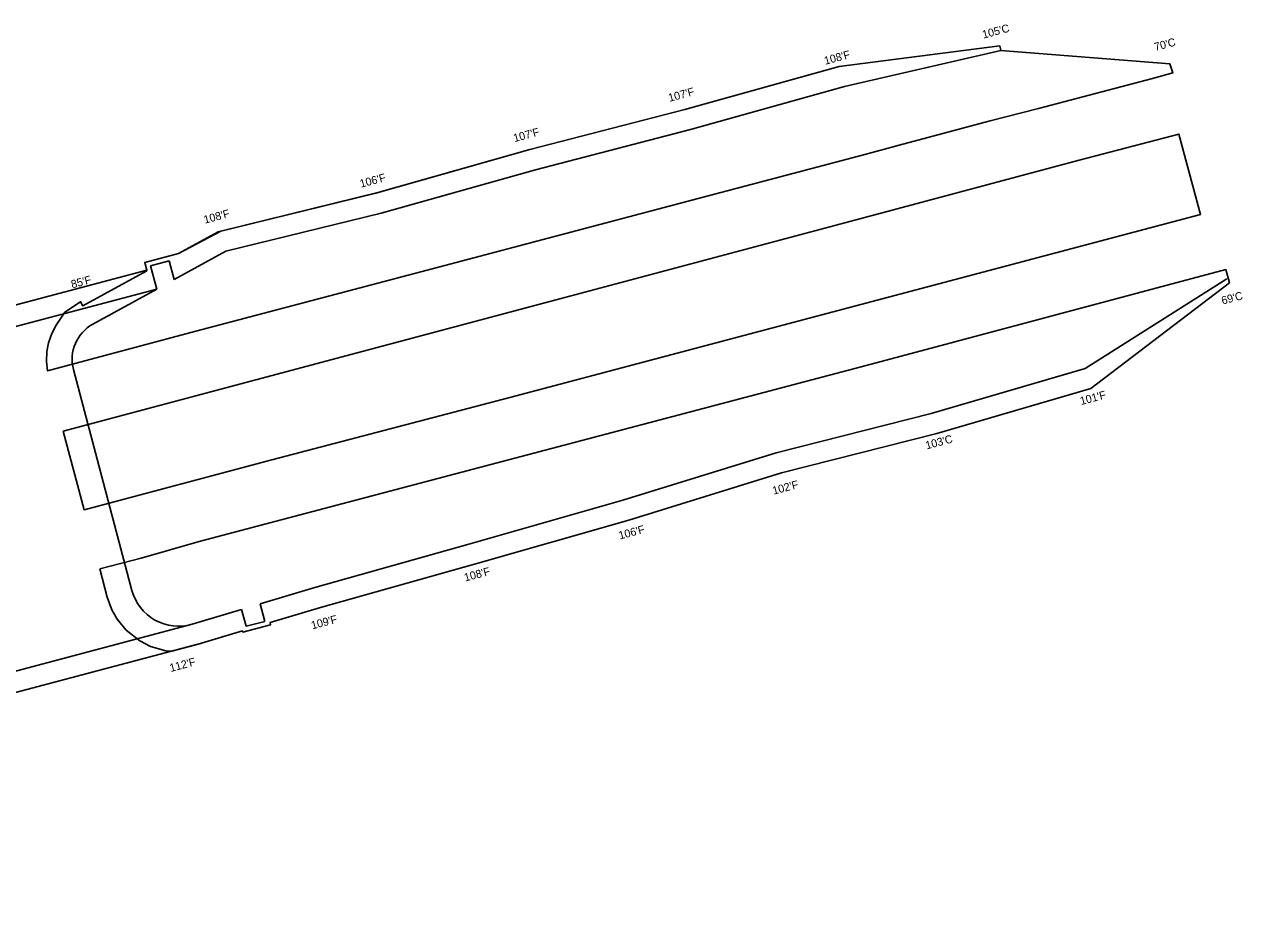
# Model space of a CAD drawing. Extents: x 2110378 to 2113376, y 867150 to 868109.
# Drawn here: x 2112615 to 2113376, y 867557 to 868109 of the extents above; entities that cross this region are included whole.
import ezdxf

# ---------------------------------------------------------------- set-up
doc = ezdxf.new("R2010")
doc.units = 0
for name, color, linetype in [('RD_PD_BCA', 7, 'Continuous'), ('RD_PD_CstnLmt', 7, 'Continuous'), ('RD_PD_DR_ErosCtrl', 7, 'Continuous'), ('RD_PD_TX_CstnLmt', 7, 'Continuous'), ('RD_Sketch1', 7, 'Continuous')]:
    doc.layers.add(name, color=color, linetype=linetype)

msp = doc.modelspace()

# ---------------------------------------------------------------- linework, layer by layer
at = {"layer": 'RD_PD_BCA'}
for p, q in [((2112015.1, 867762.57), (2112698.08, 867943.59)), ((2112108.51, 867572.24), (2112720.22, 867734.37))]:
    msp.add_line(p, q, dxfattribs=at)
at = {"layer": 'RD_PD_CstnLmt'}
for p, q in [((2113127.64, 868070.09), (2113225.16, 868092.49)), ((2113225.16, 868092.49), (2113330.72, 868084.31)), ((2113031.3, 868043.28), (2113127.64, 868070.09)), ((2112934.51, 868018.12), (2113031.3, 868043.28)), ((2112838.26, 867990.93), (2112934.51, 868018.12)), ((2112741.11, 867967.18), (2112838.26, 867990.93)), ((2112694.23, 867958.11), (2112705.83, 867961.18)), ((2112705.83, 867961.18), (2112708.92, 867949.53)), ((2112708.92, 867949.53), (2112741.11, 867967.18)), ((2112698.08, 867943.59), (2112694.23, 867958.11)), ((2113277.77, 867894), (2113366.29, 867950.1)), ((2112658.16, 867921.71), (2112698.08, 867943.59)), ((2112646.01, 867893.38), (2112682.58, 867755.41)), ((2113181.74, 867865.99), (2113277.77, 867894)), ((2113084.79, 867841.46), (2113181.74, 867865.99)), ((2112989.18, 867811.87), (2113084.79, 867841.46)), ((2112893.01, 867784.39), (2112989.18, 867811.87)), ((2112796.72, 867757.37), (2112893.01, 867784.39)), ((2112762.57, 867747.1), (2112796.72, 867757.37)), ((2112720.22, 867734.37), (2112751.07, 867743.64)), ((2112751.07, 867743.64), (2112753.88, 867733.06)), ((2112765.48, 867736.13), (2112762.57, 867747.1)), ((2112753.88, 867733.06), (2112765.48, 867736.13))]:
    msp.add_line(p, q, dxfattribs=at)
for centre, radius, start, end in [((2112670.18, 867899.79), 25, 118.73013, 194.84478), ((2112711.58, 867763.1), 30, 194.84478, 286.73431)]:
    msp.add_arc(centre, radius, start, end, dxfattribs=at)
at = {"layer": 'RD_PD_DR_ErosCtrl'}
for p, q in [((2113124.16, 868082.61), (2113224.49, 868095.41)), ((2113027.92, 868055.83), (2113124.16, 868082.61)), ((2112931.11, 868030.66), (2113027.92, 868055.83)), ((2112834.95, 868003.5), (2112931.11, 868030.66)), ((2112736.36, 867979.4), (2112834.95, 868003.5)), ((2112711.55, 867965.8), (2112736.36, 867979.4)), ((2112690.56, 867960.24), (2112711.55, 867965.8)), ((2112691.85, 867955.39), (2112690.56, 867960.24)), ((2113281.41, 867881.52), (2113367.89, 867947.57)), ((2113185.15, 867853.45), (2113281.41, 867881.52)), ((2113088.3, 867828.94), (2113185.15, 867853.45)), ((2112992.88, 867799.41), (2113088.3, 867828.94)), ((2112896.55, 867771.88), (2112992.88, 867799.41)), ((2112800.34, 867744.88), (2112896.55, 867771.88)), ((2112768.78, 867735.39), (2112800.34, 867744.88)), ((2112751.75, 867729.39), (2112769.15, 867734)), ((2112769.15, 867734), (2112768.78, 867735.39)), ((2112723.96, 867721.92), (2112751.53, 867730.21)), ((2112751.53, 867730.21), (2112751.75, 867729.39))]:
    msp.add_line(p, q, dxfattribs=at)
for points in [[(2112036.89, 867665.4), (2112026.79, 867692.41), (2112014.22, 867733.85), (2112005.83, 867753.35), (2111992.51, 867770.03), (2112691.85, 867955.39)], [(2112036.89, 867665.4), (2112044.57, 867650.18), (2112052.23, 867638.07), (2112063.87, 867594.17), (2112097.39, 867565.43), (2112103.21, 867557.38), (2112723.76, 867721.86)]]:
    msp.add_lwpolyline(points, dxfattribs=at)
at = {"layer": 'RD_Sketch1'}
for points in [[(2113225.16, 868092.49), (2113330.72, 868084.31), (2113332.69, 868078.56), (2113319.88, 868075.1), (2113248.78, 868056.44), (2113218.49, 868048.58), (2113161.74, 868033.44), (2113140.25, 868027.72), (2113050.29, 868003.88), (2112877.95, 867958.26), (2112722.43, 867917.33), (2112629.84, 867892.46), (2112629.2, 867898.31), (2112629.47, 867904.7), (2112630.46, 867909.98), (2112632.5, 867915.95), (2112635.16, 867921.12), (2112640.6, 867929.2), (2112650.47, 867935.74), (2112651.91, 867933.11), (2112691.94, 867955.05), (2112690.56, 867960.24), (2112711.55, 867965.8), (2112738.02, 867979.81), (2112836.93, 868004.21), (2112931.11, 868030.66), (2113027.92, 868055.83), (2113124.16, 868082.61), (2113224.49, 868095.41)], [(2112639.65, 867854.95), (2112652.67, 867805.8), (2112769.83, 867836.97), (2112918.5, 867875.99), (2113349.92, 867990.16), (2113336.32, 868040.39), (2113274.01, 868024.14), (2113121.52, 867983.31), (2112943.5, 867935.75)], [(2112662.46, 867768.88), (2112667.12, 867751.31), (2112670.09, 867743.24), (2112673.31, 867737.58), (2112678.93, 867730.69), (2112687.38, 867723.98), (2112694.18, 867720.52), (2112703.71, 867717.77), (2112707.47, 867717.54), (2112718.5, 867720.46), (2112723.96, 867721.92), (2112751.53, 867730.21), (2112751.75, 867729.39), (2112769.15, 867734), (2112768.78, 867735.39), (2112800.34, 867744.88), (2112896.55, 867771.88), (2112992.88, 867799.41), (2113088.3, 867828.94), (2113185.15, 867853.45), (2113281.41, 867881.52), (2113367.89, 867947.57), (2113365.67, 867955.79), (2113140.98, 867895.96), (2112910.6, 867835.19), (2112724.6, 867786.02), (2112688.35, 867775.61)]]:
    msp.add_lwpolyline(points, close=True, dxfattribs=at)

# ---------------------------------------------------------------- texts
at = {"layer": 'RD_PD_TX_CstnLmt'}
for s, p in [("105'C", (2113214.3, 868099.96)), ("70'C", (2113321.69, 868092.26)), ("108'F", (2113115.56, 868083.66)), ("107'F", (2113018.24, 868060.51)), ("107'F", (2112921.46, 868035.35)), ("106'F", (2112825.56, 868006.86)), ("108'F", (2112728.06, 867984.41)), ("85'F", (2112645.24, 867944.03)), ("69'C", (2113363.66, 867933.89)), ("101'F", (2113275.33, 867871.19)), ("103'C", (2113178.83, 867843.48)), ("102'F", (2113083.26, 867815.2)), ("106'F", (2112987.23, 867787.22)), ("108'F", (2112890.72, 867761)), ("109'F", (2112795.19, 867731.1)), ("112'F", (2112706.77, 867704.51))]:
    msp.add_text(s, height=5, rotation=14.84478, dxfattribs=at).set_placement(p)

doc.saveas('drawing.dxf')
